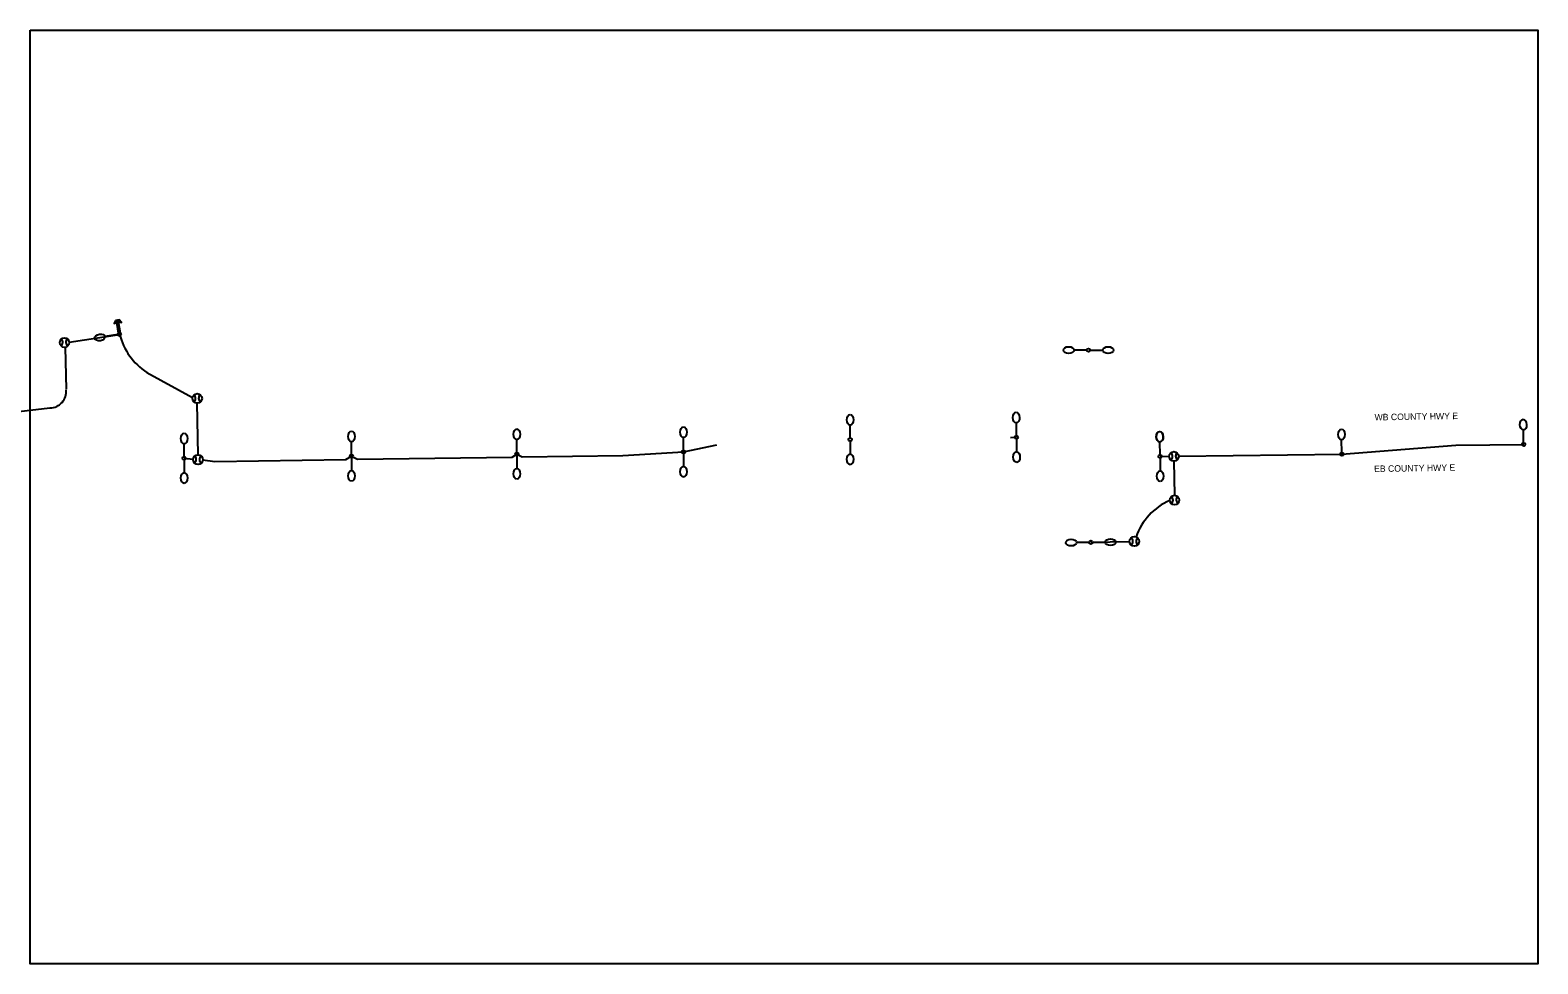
# Model space of a CAD drawing. Extents: x 589059 to 596052, y 152647 to 154942.
# Drawn here: x 594477 to 596052, y 153901 to 154876 of the extents above; entities that cross this region are included whole.
import ezdxf

# ---------------------------------------------------------------- set-up
doc = ezdxf.new("R2010")
doc.units = 0
doc.layers.add('Level 26', color=7, linetype='Continuous')
doc.layers.add('P_DRN_Flow', color=7, linetype='Continuous')

msp = doc.modelspace()

# ---------------------------------------------------------------- linework, layer by layer
at = {"layer": 'Level 26'}
for p, q in [((594517.5, 154550.4), (594569.9, 154558.5)), ((594568.1, 154558.2), (594555, 154556.2)), ((594513.3, 154544.9), (594514.2, 154501.1)), ((595580.4, 154542.1), (595567.2, 154542.1)), ((595584, 154542.1), (595597.2, 154542.1)), ((594598.5, 154518.7), (594646.2, 154492.4)), ((594652, 154432.6), (594651.2, 154486.6)), ((594464.9, 154478.1), (594497.2, 154481.7)), ((595333.3, 154450.4), (595333.3, 154463.6)), ((595507, 154452.7), (595506.9, 154466)), ((595507, 154452.7), (595506.9, 154466)), ((596036.8, 154445.4), (596036.6, 154458.6)), ((594637.5, 154430.9), (594637.5, 154444.1)), ((594812.3, 154433.1), (594812.3, 154446.3)), ((594985.1, 154435.2), (594985.1, 154448.5)), ((595159.2, 154437.5), (595159.2, 154450.7)), ((595333.3, 154446.8), (595333.3, 154433.6)), ((595507, 154449.2), (595507.1, 154436)), ((595657, 154432.8), (595656.7, 154446)), ((595657, 154432.7), (595656.9, 154446)), ((595657, 154432.7), (595656.9, 154446)), ((595847, 154435.2), (595846.7, 154448.4)), ((594637.5, 154429.1), (594647, 154428.1)), ((594637.5, 154427.3), (594637.5, 154414.1)), ((594812.3, 154429.5), (594812.3, 154416.3)), ((594985.1, 154431.7), (594985.1, 154418.5)), ((595159.2, 154433.9), (595159.2, 154420.7)), ((595657, 154429.2), (595657.2, 154416)), ((595671.5, 154426), (595672, 154390.4)), ((595583, 154341.2), (595569.7, 154341.1)), ((595584.7, 154341.3), (595599.7, 154341.5)), ((595584.8, 154341.4), (595625.2, 154342.2))]:
    msp.add_line(p, q, dxfattribs=at)
msp.add_lwpolyline([(594565.7, 154573.1), (594564.5, 154569.8), (594568, 154571.7), (594571.9, 154571), (594569.7, 154573.7)], close=True, dxfattribs=at)
for points in [[(594568.9, 154559.6), (594566.7, 154573.2)], [(594570.9, 154559.9), (594568.7, 154573.6)], [(594657, 154427.3), (594669.4, 154425.7), (594806.3, 154427.7), (594812.3, 154431.3), (594818.6, 154428), (594980.3, 154430.2), (594985.1, 154433.5), (594990.5, 154430.6), (595095.7, 154432.1), (595159.2, 154435.7), (595194, 154443.3)], [(595500.7, 154450.9), (595507, 154451)], [(595676.5, 154431.3), (595847, 154433.4), (595847, 154433.4), (595965.9, 154442.8), (596036.9, 154443.6)], [(595657, 154431), (595666.5, 154431.2)]]:
    msp.add_lwpolyline(points, dxfattribs=at)
for centre, radius in [((594512.5, 154549.9), 5), ((594569.9, 154558.5), 1.76), ((595582.2, 154542.1), 1.76), ((594651.2, 154491.6), 5), ((595507, 154451), 1.76), ((595507, 154451), 1.76), ((595159.2, 154435.7), 1.76), ((595159.2, 154435.7), 1.76), ((595333.3, 154448.6), 1.76), ((595333.3, 154448.6), 1.76), ((595671.5, 154431), 5), ((596036.9, 154443.6), 1.76), ((594637.5, 154429.1), 1.76), ((594637.5, 154429.1), 1.76), ((594652, 154427.6), 5), ((594812.3, 154431.3), 1.76), ((594812.3, 154431.3), 1.76), ((594985.1, 154433.5), 1.76), ((594985.1, 154433.5), 1.76), ((595657, 154431), 1.76), ((595657, 154431), 1.76), ((595657, 154431), 1.76), ((595847, 154433.4), 1.76), ((595672.1, 154385.4), 5), ((595584.7, 154341.3), 1.76), ((595630.2, 154342.3), 5)]:
    msp.add_circle(centre, radius, dxfattribs=at)
for centre, radius, start, end in [((594505.7, 154550), 5, 311.5526, 45.5816), ((594519, 154550.1), 5, 132.3956, 231.6258), ((594635.1, 154574.9), 67, 194.106, 236.9174), ((594497.3, 154498.7), 17, 270.7238, 6.891), ((594644.4, 154491.7), 5, 311.5526, 45.5816), ((594657.6, 154491.8), 5, 132.3956, 231.6258), ((594645.2, 154428.1), 5, 309.3835, 43.4125), ((594658.5, 154427.6), 5, 130.2265, 229.4568), ((595665, 154431.1), 5, 309.8218, 49.052), ((595678.3, 154431.4), 5, 135.8661, 229.8951), ((595665.6, 154385.4), 5, 309.8218, 49.052), ((595678.9, 154385.7), 5, 135.8661, 229.8951), ((595693.4, 154325.5), 65.1, 113.7959, 160.7437), ((595623.7, 154342.4), 5, 309.8218, 49.052), ((595637, 154342.6), 5, 135.8661, 229.8951)]:
    msp.add_arc(centre, radius, start, end, dxfattribs=at)
for centre, major_axis in [((594549.5, 154555.3), (-5.53, -0.85)), ((595561.6, 154542.1), (-5.6, 0)), ((595602.8, 154542.1), (5.6, 0)), ((595333.3, 154469.2), (0, 5.6)), ((595506.8, 154471.6), (-0.05, 5.6)), ((595506.8, 154471.6), (-0.05, 5.6)), ((596036.5, 154464.2), (-0.1, 5.59)), ((594637.5, 154449.7), (0, 5.6)), ((594812.3, 154451.9), (0, 5.6)), ((594985.1, 154454.1), (0, 5.6)), ((595159.2, 154456.3), (0, 5.6)), ((595656.6, 154451.6), (-0.1, 5.59)), ((595656.9, 154451.6), (-0.05, 5.6)), ((595656.9, 154451.6), (-0.05, 5.6)), ((595846.6, 154454), (-0.1, 5.59)), ((595507.2, 154430.4), (0.05, -5.6)), ((595159.2, 154415.1), (0, -5.6)), ((595333.3, 154428), (0, -5.6)), ((594637.5, 154408.5), (0, -5.6)), ((594812.3, 154410.7), (0, -5.6)), ((594985.1, 154412.9), (0, -5.6)), ((595657.2, 154410.4), (0.05, -5.6)), ((595564.1, 154341), (-5.6, -0.07)), ((595605.3, 154341.5), (5.6, 0.07))]:
    msp.add_ellipse(centre, major_axis=major_axis, ratio=0.621156, dxfattribs=at)
at = {"layer": 'P_DRN_Flow'}
msp.add_lwpolyline([(594476.7, 154876.2), (596051.7, 154876.2), (596051.7, 153901.2), (594476.7, 153901.2)], close=True, dxfattribs=at)

# ---------------------------------------------------------------- texts
for s, p in [('WB COUNTY HWY E', (595881.2, 154468.6)), ('EB COUNTY HWY E', (595880.7, 154414.7))]:
    msp.add_text(s, height=6.75, rotation=0.9238, dxfattribs=at).set_placement(p)

doc.saveas('drawing.dxf')
